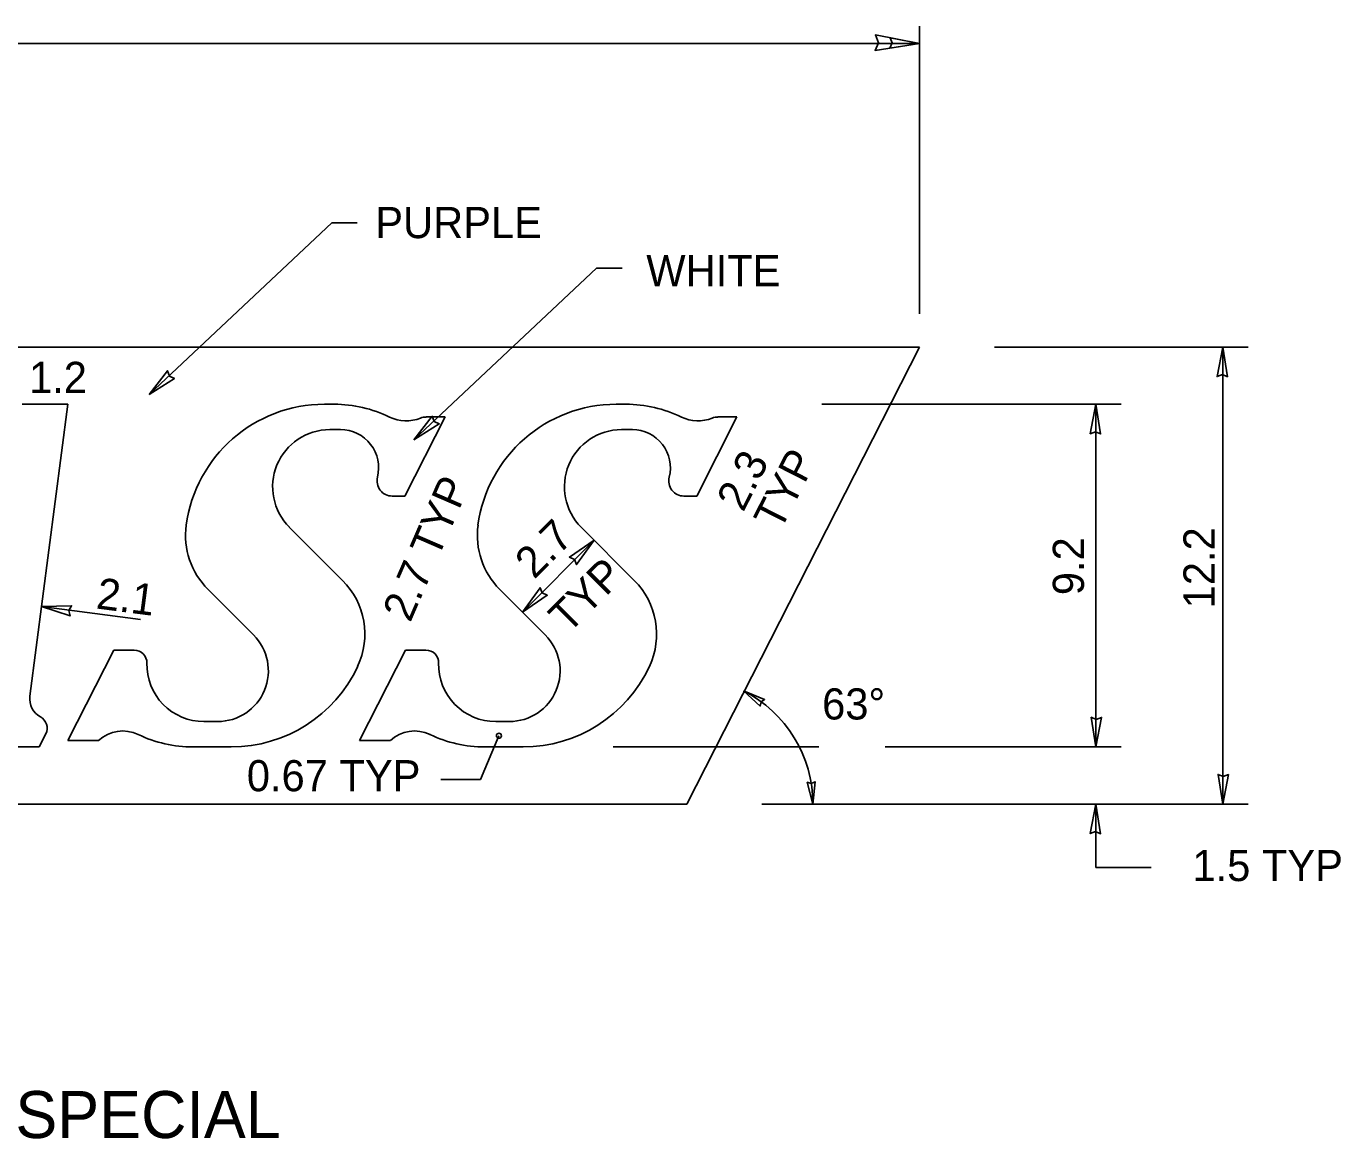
# Model space of a CAD drawing. Extents: x 10268197 to 10268826, y 2141503 to 2142677.
# Drawn here: x 10268526.03 to 10268550.16, y 2142338.69 to 2142359.1 of the extents above; entities that cross this region are included whole.
import ezdxf

# ---------------------------------------------------------------- set-up
doc = ezdxf.new("R2010")
doc.units = 0
doc.layers.add('Default', color=7, linetype='Continuous')
doc.layers.add('TextDetails', color=7, linetype='Continuous')

msp = doc.modelspace()

# ---------------------------------------------------------------- linework, layer by layer
at = {"layer": 'Default'}
for p, q in [((10268542.432, 2142353.829), (10268542.432, 2142359.103)), ((10268501.67, 2142358.79), (10268542.432, 2142358.79)), ((10268542.432, 2142353.216), (10268517.161, 2142353.216)), ((10268538.161, 2142344.832), (10268542.432, 2142353.216)), ((10268543.806, 2142353.216), (10268548.464, 2142353.216)), ((10268547.998, 2142344.832), (10268547.998, 2142353.216)), ((10268525.961, 2142352.168), (10268526.799, 2142352.168)), ((10268526.799, 2142352.168), (10268526.101, 2142346.809)), ((10268531.51, 2142352.168), (10268531.687, 2142352.168)), ((10268533.726, 2142351.935), (10268532.985, 2142350.483)), ((10268533.377, 2142351.935), (10268533.726, 2142351.935)), ((10268536.866, 2142352.168), (10268537.043, 2142352.168)), ((10268539.081, 2142351.935), (10268538.341, 2142350.483)), ((10268538.732, 2142351.935), (10268539.081, 2142351.935)), ((10268540.638, 2142352.168), (10268546.135, 2142352.168)), ((10268545.67, 2142345.881), (10268545.67, 2142352.168)), ((10268531.804, 2142351.702), (10268531.605, 2142351.702)), ((10268537.161, 2142351.702), (10268536.96, 2142351.702)), ((10268532.985, 2142350.483), (10268532.751, 2142350.483)), ((10268538.341, 2142350.483), (10268538.108, 2142350.483)), ((10268530.863, 2142349.913), (10268531.84, 2142348.937)), ((10268536.219, 2142349.913), (10268537.196, 2142348.937)), ((10268535.143, 2142348.355), (10268536.461, 2142349.672)), ((10268530.206, 2142347.936), (10268529.368, 2142348.773)), ((10268535.561, 2142347.936), (10268534.723, 2142348.773)), ((10268526.316, 2142348.457), (10268528.133, 2142348.22)), ((10268526.796, 2142345.997), (10268527.642, 2142347.656)), ((10268527.642, 2142347.656), (10268528.015, 2142347.656)), ((10268532.151, 2142345.997), (10268532.997, 2142347.656)), ((10268532.997, 2142347.656), (10268533.371, 2142347.656)), ((10268529.295, 2142346.346), (10268529.546, 2142346.346)), ((10268534.653, 2142346.346), (10268534.903, 2142346.346)), ((10268526.394, 2142346.119), (10268526.27, 2142345.88)), ((10268527.362, 2142345.997), (10268526.796, 2142345.997)), ((10268532.717, 2142345.997), (10268532.151, 2142345.997)), ((10268534.371, 2142345.286), (10268534.712, 2142346.085)), ((10268526.27, 2142345.88), (10268523.942, 2142345.88)), ((10268529.797, 2142345.88), (10268529.097, 2142345.88)), ((10268535.152, 2142345.88), (10268534.453, 2142345.88)), ((10268536.808, 2142345.881), (10268540.584, 2142345.881)), ((10268541.801, 2142345.881), (10268546.135, 2142345.881)), ((10268533.647, 2142345.286), (10268534.371, 2142345.286)), ((10268516.394, 2142344.832), (10268538.161, 2142344.832)), ((10268539.536, 2142344.832), (10268548.464, 2142344.832)), ((10268545.67, 2142343.669), (10268545.67, 2142344.832)), ((10268545.67, 2142343.669), (10268546.683, 2142343.669))]:
    msp.add_line(p, q, dxfattribs=at)
for points in [[(10268542.432, 2142358.79), (10268541.616, 2142358.661), (10268541.678, 2142358.801), (10268541.622, 2142358.946)], [(10268542.432, 2142358.79), (10268541.888, 2142358.704), (10268541.929, 2142358.797), (10268541.892, 2142358.894)], [(10268547.998, 2142353.216), (10268548.084, 2142352.672), (10268547.991, 2142352.713), (10268547.894, 2142352.675)], [(10268528.289, 2142352.347), (10268528.626, 2142352.782), (10268528.661, 2142352.686), (10268528.754, 2142352.641)], [(10268533.15, 2142351.514), (10268533.487, 2142351.949), (10268533.522, 2142351.853), (10268533.615, 2142351.808)], [(10268545.67, 2142352.168), (10268545.756, 2142351.624), (10268545.662, 2142351.665), (10268545.565, 2142351.628)], [(10268536.461, 2142349.672), (10268536.136, 2142349.226), (10268536.1, 2142349.321), (10268536.005, 2142349.363)], [(10268535.143, 2142348.355), (10268535.467, 2142348.801), (10268535.504, 2142348.706), (10268535.599, 2142348.663)], [(10268526.316, 2142348.457), (10268526.866, 2142348.472), (10268526.814, 2142348.385), (10268526.838, 2142348.283)], [(10268539.203, 2142346.908), (10268539.586, 2142346.751), (10268539.523, 2142346.707), (10268539.509, 2142346.631)], [(10268545.67, 2142345.881), (10268545.584, 2142346.425), (10268545.677, 2142346.384), (10268545.774, 2142346.421)], [(10268540.474, 2142344.832), (10268540.372, 2142345.233), (10268540.444, 2142345.209), (10268540.514, 2142345.243)], [(10268547.998, 2142344.832), (10268547.913, 2142345.377), (10268548.006, 2142345.336), (10268548.103, 2142345.373)], [(10268545.67, 2142344.832), (10268545.756, 2142344.289), (10268545.662, 2142344.33), (10268545.565, 2142344.292)]]:
    msp.add_lwpolyline(points, close=True, dxfattribs=at)
for points in [[(10268532.11, 2142355.497), (10268531.643, 2142355.497), (10268528.289, 2142352.347)], [(10268536.972, 2142354.664), (10268536.504, 2142354.664), (10268533.15, 2142351.514)]]:
    msp.add_lwpolyline(points, dxfattribs=at)
msp.add_circle((10268534.712, 2142346.086), 0.0466, dxfattribs=at)
for centre, radius, start, end in [((10268531.509, 2142349.606), 2.562, 90, 172.3089), ((10268531.686, 2142349.839), 2.329, 64.0896, 90), ((10268533.376, 2142351.655), 0.279, 90, 112.0347), ((10268536.865, 2142349.606), 2.562, 90, 172.3089), ((10268537.042, 2142349.839), 2.329, 64.0896, 90), ((10268538.732, 2142351.655), 0.279, 90, 112.0347), ((10268531.605, 2142350.654), 1.048, 90, 225), ((10268531.804, 2142351.003), 0.699, 345.6915, 90), ((10268533.009, 2142352.562), 0.699, 244.0896, 292.0347), ((10268536.961, 2142350.654), 1.048, 90, 225), ((10268537.16, 2142351.003), 0.699, 345.6915, 90), ((10268538.365, 2142352.562), 0.699, 244.0896, 292.0347), ((10268532.752, 2142350.762), 0.279, 165.6915, 270), ((10268538.108, 2142350.762), 0.279, 165.6915, 270), ((10268530.356, 2142349.762), 1.397, 172.3089, 225), ((10268535.712, 2142349.762), 1.397, 172.3089, 225), ((10268530.852, 2142347.949), 1.397, 334.95, 45), ((10268536.208, 2142347.949), 1.397, 334.95, 45), ((10268529.547, 2142347.277), 0.931, 270, 45), ((10268534.903, 2142347.277), 0.931, 270, 45), ((10268528.015, 2142347.424), 0.233, 358.6664, 90), ((10268533.371, 2142347.424), 0.233, 358.6664, 90), ((10268529.296, 2142347.394), 1.048, 178.6665, 270), ((10268529.797, 2142348.442), 2.562, 270, 334.95), ((10268534.652, 2142347.394), 1.048, 178.6665, 270), ((10268535.153, 2142348.442), 2.562, 270, 334.95), ((10268538.146, 2142344.833), 2.329, 0, 63.0012), ((10268526.471, 2142346.76), 0.373, 172.5884, 241.8673), ((10268526.185, 2142346.226), 0.233, 332.9784, 61.8673), ((10268527.808, 2142345.521), 0.652, 64.3795, 133.1892), ((10268533.164, 2142345.521), 0.652, 64.3795, 133.1892), ((10268529.096, 2142348.209), 2.329, 244.3795, 270), ((10268534.452, 2142348.209), 2.329, 244.3795, 270)]:
    msp.add_arc(centre, radius, start, end, dxfattribs=at)

# ---------------------------------------------------------------- texts
for s, p in [('PURPLE', (10268532.441, 2142355.216)), ('WHITE', (10268537.416, 2142354.334)), ('1.2', (10268526.085, 2142352.375)), ('63°', (10268540.644, 2142346.384)), ('0.67 TYP', (10268530.083, 2142345.067)), ('1.5 TYP', (10268547.442, 2142343.419))]:
    msp.add_text(s, height=0.5717, dxfattribs=at).set_placement(p)
for s, rotation, p in [('2.3', 63, (10268539.194, 2142350.173)), ('TYP', 63, (10268539.876, 2142349.825)), ('2.7 TYP', 66.578, (10268533.082, 2142348.149)), ('2.7', 45, (10268535.359, 2142348.944)), ('12.2', 90, (10268547.848, 2142348.423)), ('9.2', 90, (10268545.45, 2142348.665)), ('TYP', 45, (10268535.981, 2142347.942)), ('2.1', 352.5994, (10268527.302, 2142348.423))]:
    msp.add_text(s, height=0.5717, rotation=rotation, dxfattribs=at).set_placement(p)
at = {"layer": 'TextDetails'}
msp.add_text('LOGO EP-SPECIAL', height=0.8624, dxfattribs=at).set_placement((10268520.259, 2142338.704))

doc.saveas('drawing.dxf')
